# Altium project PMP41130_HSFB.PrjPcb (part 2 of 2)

## Sheet PMP41130_CTRL.SchDoc
size 431 x 279 mm; Date: Not shown in title block; ApprovedBy: Not shown in title block; CheckedBy: Not shown in title block; Author: Not shown in title block; CompanyName: Not shown in title block; Engineer: Not shown in title block; Organization: Not shown in title block; Address1: Not shown in title block; Address2: Not shown in title block; Address3: Not shown in title block; Address4: Not shown in title block; DocumentNumber: 2; Revision: Use project parameter SCH_Rev; SheetNumber: 3; SheetTotal: 5; PageSetup: Record=PageOptions¦CenterHorizontal=True¦CenterVertical=True¦PrintScale=1.00¦XCorrection=1.00¦YCorrection=1.00¦PrintKind=0¦BorderSize=5000000¦LeftOffset=0¦BottomOffset=0¦Orientation=2¦PaperLength=1000¦PaperWidth=1000¦Scale=100¦PaperSource=15¦PrintQuality=600¦MediaType=1¦DitherType=10¦PaperKind=Letter¦PrintScaleMode=1
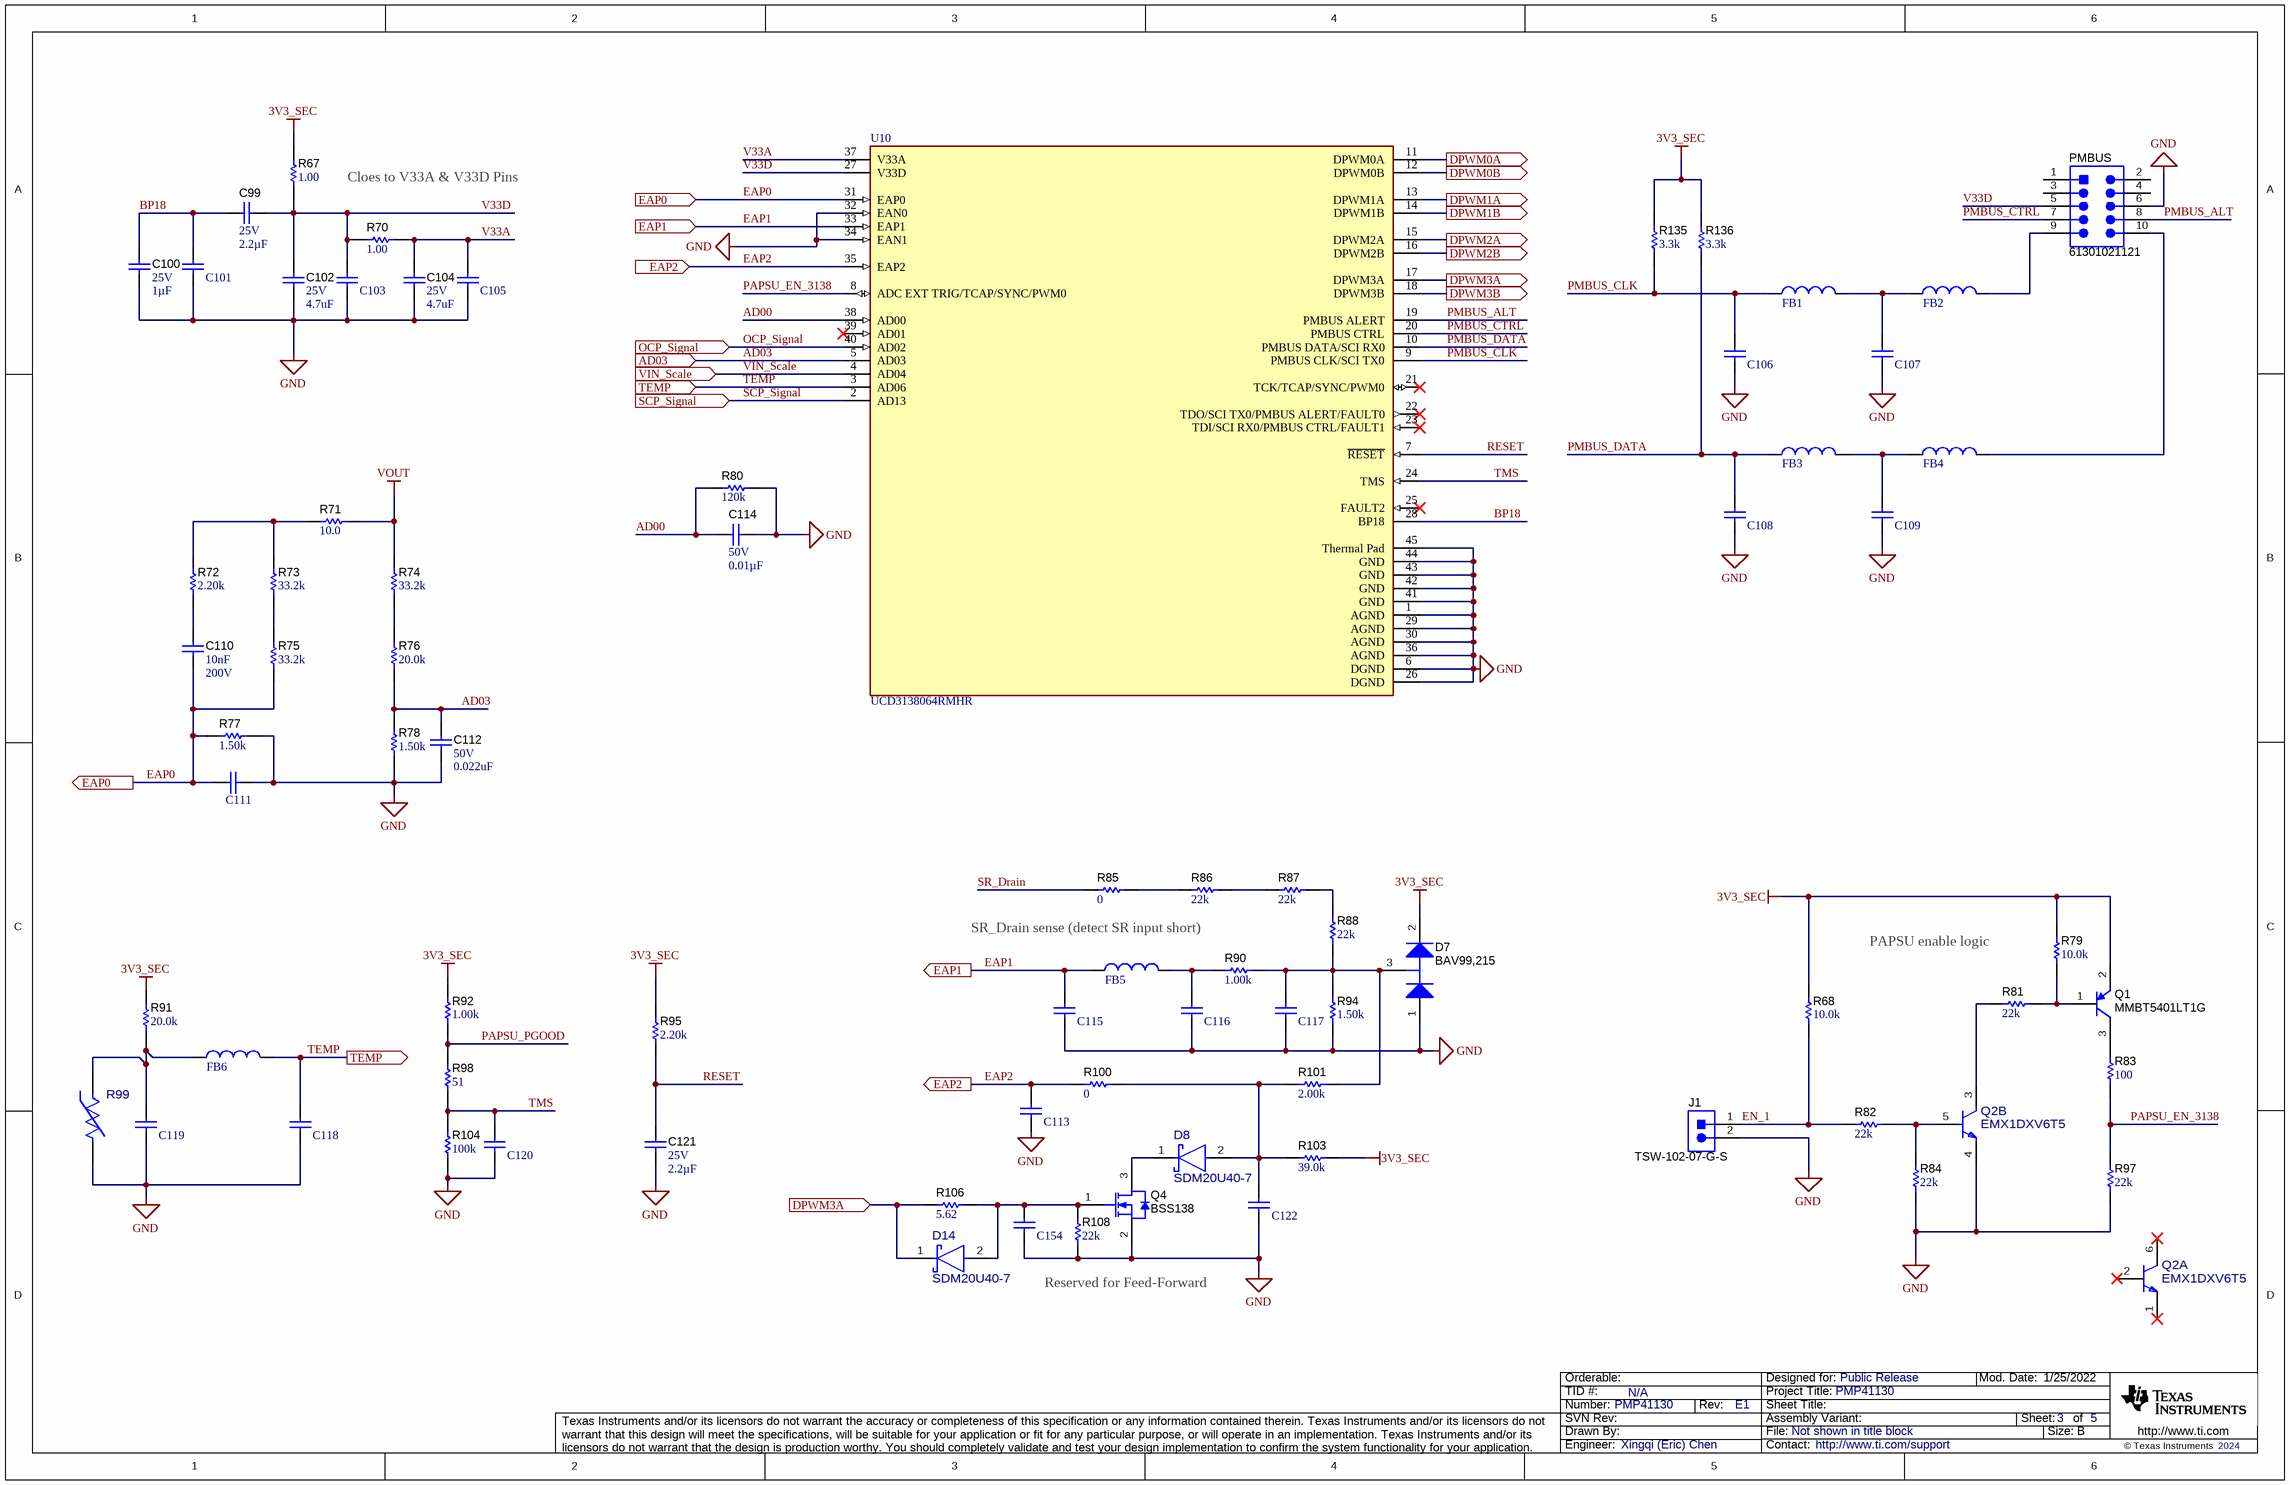
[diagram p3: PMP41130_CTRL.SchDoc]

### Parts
C99  VDC_V: 25V  ValueDisplayed: 2.2µF  [0402]  (hidden comment: GRM155R61E225ME15D)
C100  VDC_V: 25V  ValueDisplayed: 1µF  [0402]  (hidden comment: GRM155R61E105MA12D)
C101  885012205050  [WCAP-CSGP_0402_L1W0.5H0.5]  (value not drawn)
C102  VDC_V: 25V  ValueDisplayed: 4.7uF  [0402]  (hidden comment: GRM155R61E475ME15)
C103  885012205050  [WCAP-CSGP_0402_L1W0.5H0.5]  (value not drawn)
C104  VDC_V: 25V  ValueDisplayed: 4.7uF  [0402]  (hidden comment: GRM155R61E475ME15)
C105  885012205050  [WCAP-CSGP_0402_L1W0.5H0.5]  (value not drawn)
C106  885012005058  [WCAP-CSGP_0402_L1W0.5H0.5]  (value not drawn)
C107  885012005058  [WCAP-CSGP_0402_L1W0.5H0.5]  (value not drawn)
C108  885012005058  [WCAP-CSGP_0402_L1W0.5H0.5]  (value not drawn)
C109  885012005058  [WCAP-CSGP_0402_L1W0.5H0.5]  (value not drawn)
C110  Cap_F: 10nF  VDC_V: 200V  [0603]  (hidden comment: C0603C103K2RACTU)
C111  885012005067  [WCAP-CSGP_0402_L1W0.5H0.5]  (value not drawn)
C112  VDC_V: 50V  ValueDisplayed: 0.022uF  [0402]  (hidden comment: GRM155R71H223KA12D)
C113  885392005114  [WCAP-CSRF_0402_L1W0.5H0.5]  (value not drawn)
C114  VDC_V: 50V  ValueDisplayed: 0.01µF  [0402]  (hidden comment: CGA2B3X8R1H103K050BB)
C115  885012005055  [WCAP-CSGP_0402_L1W0.5H0.5]  (value not drawn)
C116  885012005055  [WCAP-CSGP_0402_L1W0.5H0.5]  (value not drawn)
C117  885012005055  [WCAP-CSGP_0402_L1W0.5H0.5]  (value not drawn)
C118  885012205092  [WCAP-CSGP_0402_L1W0.5H0.5]  (value not drawn)
C119  885012005067  [WCAP-CSGP_0402_L1W0.5H0.5]  (value not drawn)
C120  885012205044  [WCAP-CSGP_0402_L1W0.5H0.5]  (value not drawn)
C121  VDC_V: 25V  ValueDisplayed: 2.2µF  [0402]  (hidden comment: GRM155R61E225ME15D)
C122  885012205062  [WCAP-CSGP_0402_L1W0.5H0.5]  (value not drawn)
C154  885012205092  [WCAP-CSGP_0402_L1W0.5H0.5]  (value not drawn)
D7  BAV99,215  [SOT-23L]
D8  SDM20U40-7  [FP-SDM20U40-7_SOD523-MFG]
D14  SDM20U40-7  [FP-SDM20U40-7_SOD523-MFG]
FB1  7427927141  [WE-CBF_0402_L1W0.5H0.5_HS/WB]  (value not drawn)
FB2  7427927141  [WE-CBF_0402_L1W0.5H0.5_HS/WB]  (value not drawn)
FB3  7427927141  [WE-CBF_0402_L1W0.5H0.5_HS/WB]  (value not drawn)
FB4  7427927141  [WE-CBF_0402_L1W0.5H0.5_HS/WB]  (value not drawn)
FB5  7427927141  [WE-CBF_0402_L1W0.5H0.5_HS/WB]  (value not drawn)
FB6  7427927141  [WE-CBF_0402_L1W0.5H0.5_HS/WB]  (value not drawn)
J1  TSW-102-07-G-S  [TSW-102-07-G-S]
PMBUS  61301021121  [WURTH_61301021121]
Q1  MMBT5401LT1G  [SOT-23]
Q2  EMX1DXV6T5  [FP-EMX1DXV6T5_SOT563-MFG]  (parts A,B of 2)
Q4  BSS138  [SOT-23]
R67  ValueDisplayed: 1.00  [0402]  (hidden comment: CRCW04021R00FKED)
R68  ValueDisplayed: 10.0k  [0402]  (hidden comment: ERJ-2RKF1002X)
R70  ValueDisplayed: 1.00  [0402]  (hidden comment: CRCW04021R00FKED)
R71  ValueDisplayed: 10.0  [0402]  (hidden comment: RK73H1ETTP10R0F)
R72  ValueDisplayed: 2.20k  [0402]  (hidden comment: ERJ-2RKF2201X)
R73  ValueDisplayed: 33.2k  [0402]  (hidden comment: CRCW040233K2FKED)
R74  ValueDisplayed: 33.2k  [0402]  (hidden comment: CRCW040233K2FKED)
R75  ValueDisplayed: 33.2k  [0402]  (hidden comment: CRCW040233K2FKED)
R76  ValueDisplayed: 20.0k  [0402]  (hidden comment: RT0402BRD0720KL)
R77  ValueDisplayed: 1.50k  [0402]  (hidden comment: ERJ-2RKF1501X)
R78  ValueDisplayed: 1.50k  [0402]  (hidden comment: ERJ-2RKF1501X)
R79  ValueDisplayed: 10.0k  [0402]  (hidden comment: ERJ-2RKF1002X)
R80  ValueDisplayed: 120k  [0402]  (hidden comment: ERJ-2RKF1203X)
R81  ValueDisplayed: 22k  [0402]  (hidden comment: CRCW040222K0JNED)
R82  ValueDisplayed: 22k  [0402]  (hidden comment: CRCW040222K0JNED)
R83  ValueDisplayed: 100  [0402]  (hidden comment: RC0402FR-07100RL)
R84  ValueDisplayed: 22k  [0402]  (hidden comment: CRCW040222K0JNED)
R85  ValueDisplayed: 0  [0402]  (hidden comment: RC0402JR-070RL)
R86  ValueDisplayed: 22k  [0402]  (hidden comment: CRCW040222K0JNED)
R87  ValueDisplayed: 22k  [0402]  (hidden comment: CRCW040222K0JNED)
R88  ValueDisplayed: 22k  [0402]  (hidden comment: CRCW040222K0JNED)
R90  ValueDisplayed: 1.00k  [0402]  (hidden comment: ERJ-2RKF1001X)
R91  ValueDisplayed: 20.0k  [0402]  (hidden comment: RT0402BRD0720KL)
R92  ValueDisplayed: 1.00k  [0402]  (hidden comment: ERJ-2RKF1001X)
R94  ValueDisplayed: 1.50k  [0402]  (hidden comment: ERJ-2RKF1501X)
R95  ValueDisplayed: 2.20k  [0402]  (hidden comment: ERJ-2RKF2201X)
R97  ValueDisplayed: 22k  [0402]  (hidden comment: CRCW040222K0JNED)
R98  ValueDisplayed: 51  [0402]  (hidden comment: RC0402JR-0751RL)
R99  NCU15WF104E6SRC  [FP-NCU15WF104E6SRC_0402-MFG]  (value not drawn)
R100  ValueDisplayed: 0  [0402]  (hidden comment: RC0402JR-070RL)
R101  ValueDisplayed: 2.00k  [0402]  (hidden comment: RG1005P-202-B-T5)
R103  ValueDisplayed: 39.0k  [0402]  (hidden comment: ERJ2RKF3902X)
R104  ValueDisplayed: 100k  [0402]  (hidden comment: RC0402FR-07100KL)
R106  ValueDisplayed: 5.62  [0402]  (hidden comment: CRCW04025R62FKED)
R108  ValueDisplayed: 22k  [0402]  (hidden comment: CRCW040222K0JNED)
R135  ValueDisplayed: 3.3k  [0402]  (hidden comment: CRCW04023K30JNED)
R136  ValueDisplayed: 3.3k  [0402]  (hidden comment: CRCW04023K30JNED)
U10  UCD3138064RMHR  [FP-RMH0040A-MFG]

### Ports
AD03 (in), DPWM0A (out), DPWM0B (out), DPWM1A (out), DPWM1B (out), DPWM2A (out), DPWM2B (out), DPWM3A (in), DPWM3A (out), DPWM3B (out), EAP0 (in), EAP0 (out), EAP1 (in), EAP1 (out), EAP2 (in), EAP2 (out), OCP_Signal (in), SCP_Signal (in), TEMP (in), TEMP (out), VIN_Scale (in)

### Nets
3V3_SEC: D7.2(K) Q1.2(E) R67.2 R68.2 R79.2 R91.2 R92.2 R95.2 R103.2 R135.2 R136.2
GND: C100.2 C101.2 C102.2 C103.2 C104.2 C105.2 C106.2 C107.2 C108.2 C109.2 C111.2 C112.2 C113.2 C114.1 C115.2 C116.2 C117.2 C118.2 C119.2 C120.2 C121.2 C122.2 C154.2 D7.1(A) J1.2 PMBUS.6 Q2.4(EMITTER_2) Q4.2(S) R77.2 R78.1 R80.2 R84.1 R94.1 R97.1 R99.2 R104.1 R108.1 U10.1(AGND) U10.6(DGND) U10.26(DGND) U10.29(AGND) U10.30(AGND) U10.32(EAN0) U10.34(EAN1) U10.36(AGND) U10.41(GND) U10.42(GND) U10.43(GND) U10.44(GND) U10.45(Thermal_Pad)
VOUT: R71.2 R74.2
AD00: C114.2 R80.1 U10.38(AD00)
AD03: C112.1 R76.1 R78.2 U10.5(AD03) ; port AD03
BP18: C99.2 C100.1 C101.1 U10.28(BP18)
DPWM0A: U10.11(DPWM0A) ; port DPWM0A
DPWM0B: U10.12(DPWM0B) ; port DPWM0B
DPWM1A: U10.13(DPWM1A) ; port DPWM1A
DPWM1B: U10.14(DPWM1B) ; port DPWM1B
DPWM2A: U10.15(DPWM2A) ; port DPWM2A
DPWM2B: U10.16(DPWM2B) ; port DPWM2B
DPWM3A: D14.1(CATHODE) R106.1 U10.17(DPWM3A) ; port DPWM3A
DPWM3B: U10.18(DPWM3B) ; port DPWM3B
EAP0: C110.2 C111.1 R75.1 R77.1 U10.31(EAP0) ; port EAP0
EAP1: C115.1 FB5.1 U10.33(EAP1) ; port EAP1
EAP2: C113.1 R100.1 U10.35(EAP2) ; port EAP2
EN_1: J1.1 R68.1 R82.2
OCP_Signal: U10.40(AD02) ; port OCP_Signal
PAPSU_EN_3138: R83.1 R97.2 U10.8(ADC_EXT_TRIG/TCAP/SYNC/PWM0)
PAPSU_PGOOD: R92.1 R98.2
PMBUS_ALT: PMBUS.8 U10.19(PMBUS_ALERT)
PMBUS_CLK: C106.1 FB1.1 R135.1 U10.9(PMBUS_CLK/SCI_TX0)
PMBUS_CTRL: PMBUS.7 U10.20(PMBUS_CTRL)
PMBUS_DATA: C108.1 FB3.1 R136.1 U10.10(PMBUS_DATA/SCI_RX0)
RESET: C121.1 R95.1 U10.7(~{RESET})
SCP_Signal: U10.2(AD13) ; port SCP_Signal
SR_Drain: R85.1
TEMP: C118.1 FB6.2 U10.3(AD06) ; port TEMP
TMS: C120.1 R98.1 R104.2 U10.24(TMS)
V33A: C104.1 C105.1 R70.2 U10.37(V33A)
V33D: C99.1 C102.1 C103.1 PMBUS.5 R67.1 R70.1 U10.27(V33D)
VIN_Scale: U10.4(AD04) ; port VIN_Scale
NetC107_1: C107.1 FB1.2 FB2.1
NetC109_1: C109.1 FB3.2 FB4.1
NetC110_1: C110.1 R72.1
NetC116_1: C116.1 FB5.2 R90.1
NetC117_1: C117.1 D7.3(C) R88.1 R90.2 R94.2 R101.2
NetC119_1: C119.1 FB6.1 R91.1 R99.1
NetC122_1: C122.1 D8.2(ANODE) R100.2 R101.1 R103.1
NetC154_1: C154.1 D14.2(ANODE) Q4.1(G) R106.2 R108.2
NetD8_1: D8.1(CATHODE) Q4.3(D)
NetFB2_2: FB2.2 PMBUS.9
NetFB4_2: FB4.2 PMBUS.10
NetQ1_1: Q1.1(B) R79.1 R81.2
NetQ1_3: Q1.3(C) R83.2
NetQ2_3: Q2.3(COLLECTOR_2) R81.1
NetQ2_5: Q2.5(BASE_2) R82.1 R84.2
NetR71_1: R71.1 R72.2 R73.2
NetR73_1: R73.1 R75.2
NetR74_1: R74.1 R76.2
NetR85_2: R85.2 R86.1
NetR86_2: R86.2 R87.1
NetR87_2: R87.2 R88.2

Not connected (* = marked no-connect by the designer): PMBUS 1 2 3 4; Q2 1(EMITTER_1)* 2(BASE_1)* 6(COLLECTOR_1)*; U10 21(TCK/TCAP/SYNC/PWM0)* 22(TDO/SCI_TX0/PMBUS_ALERT/FAULT0)* 23(TDI/SCI_RX0/PMBUS_CTRL/FAULT1)* 25(FAULT2)* 39(AD01)*

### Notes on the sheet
- Cloes to V33A & V33D Pins
- SR_Drain sense (detect SR input short)
- PAPSU enable logic
- Reserved for Feed-Forward

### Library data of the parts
C99 C121 = CMP-0081010-1: CAP, CERM, 2.2 µF, 25 V,+/- 20%, X5R, 0402; Manufacturer: MuRata; SizeAreaWB_mm2: 3; SizeArea_mm2: 0.5; AEC Qualified: N; AEC Category: Q200; Value: 2.2uF; TaMax_C: 85°C; SizeZ_mm: 0.6; TaMin_C: -55°C; U/M: EA; SizeX_mm: 1
C100 = CMP-0078625-1: CAP, CERM, 1 µF, 25 V,+/- 20%, X5R, 0402; Manufacturer: MuRata; SizeAreaWB_mm2: 3; SizeArea_mm2: 0.5; AEC Qualified: N; AEC Category: Q200; Value: 1uF; TaMax_C: 85°C; SizeZ_mm: 0.6; TaMin_C: -55°C; U/M: EA; SizeX_mm: 1
C101 C103 C105 = CMP-0119280-1: WCAP-CSGP Multilayer Ceramic Chip Capacitor, General Purpose, size 0402, X7R, 10nF, 25VDC; Manufacturer: Wurth Elektronik; Capacitance Tolerance: +/-10%; Case/Size Code: 0402; Dissipation Factor: 3.5%; Insulation Resistance: 10GOhm; Rated Voltage (DC): 25V; Technical Reference: X7R0402103K025DFCT10000
C102 C104 = CMP-0006612-2: CAP, CERM, 4.7 uF, 25 V, +/- 20%, X5R, 0402; Manufacturer: MuRata; TaMin_C: -55°C; Polarized: N; SizeAreaWB_mm2: 3; Value1: Unknown; U/M: EA; Value: 4.7uF; TaMax_C: 85°C; SizeZ_mm: 0.6; SizeX_mm: 1; SizeY_mm: 0.5; Cap_F: 4.7µF; AEC Category: Q200
C106-C109 = CMP-0104156-1: WCAP-CSGP Multilayer Ceramic Chip Capacitor, General Purpose, size 0402, NP0, 33pF, 50VDC; Manufacturer: Wurth Elektronik; Capacitance Tolerance: +/-5%; Case/Size Code: 0402; Insulation Resistance: 10GOhm; Q Factor: 1000; Rated Voltage (DC): 50V; Technical Reference: NP00402330J050DFCT10000
C110 = CMP-0006852-4: CAP, CERM, 0.01 uF, 200 V, +/- 10%, X7R, 0603; Manufacturer: Kemet; TaMin_C: -55°C; Polarized: N; SizeAreaWB_mm2: 4.68; Value1: Unknown; U/M: EA; Value: 0.01uF; TaMax_C: 125°C; SizeZ_mm: 1; SizeX_mm: 1.6; SizeY_mm: 0.8; SizeArea_mm2: 1.28; AEC Category: Q200
C111 C119 = CMP-0107736-1: WCAP-CSGP Multilayer Ceramic Chip Capacitor, General Purpose, size 0402, NP0, 1nF, 50VDC; Manufacturer: Wurth Elektronik; Capacitance Tolerance: +/-5%; Case/Size Code: 0402; Insulation Resistance: 10GOhm; Q Factor: 1000; Rated Voltage (DC): 50V; Technical Reference: NP00402102J050DFCT10000
C112 = CMP-0006684-2: CAP, CERM, 0.022 uF, 50 V, +/- 10%, X7R, 0402; Manufacturer: MuRata; TaMin_C: -55°C; Polarized: N; SizeAreaWB_mm2: 3; Value1: Unknown; U/M: EA; TaMax_C: 125°C; SizeZ_mm: 0.6; SizeX_mm: 1; SizeY_mm: 0.5; Cap_F: 22nF; AEC Category: Q200
C113 = CMP-0116016-1: WCAP-CSRF Multilayer Ceramic Chip Capacitor, High Frequency, size 0402, NP0 Class I, 22pF, 50VDC; Manufacturer: Wurth Elektronik; Capacitance Tolerance: +/-5%; Case/Size Code: 0402; Insulation Resistance: 10GOhm; Q Factor: 840; Rated Voltage (DC): 50V; Technical Reference: NP00402220J050DFCT1R000
C114 = CMP-0078224-1: CAP, CERM, 0.01 µF, 50 V,+/- 10%, X8R, AEC-Q200 Grade 0, 0402; Manufacturer: TDK; TaMin_C: -55°C; Polarized: N; SizeAreaWB_mm2: 3; U/M: EA; Value: 0.01uF; TaMax_C: 150°C; SizeZ_mm: 0.6; SizeX_mm: 1; SizeY_mm: 0.5; AEC Qualified: Y; Cap_F: 10nF; AEC Grade: 0; AEC Category: Q200
C115-C117 = CMP-0111322-1: WCAP-CSGP Multilayer Ceramic Chip Capacitor, General Purpose, size 0402, NP0, 10pF, 50VDC; Manufacturer: Wurth Elektronik; Capacitance Tolerance: +/-5%; Case/Size Code: 0402; Insulation Resistance: 10GOhm; Q Factor: 600; Rated Voltage (DC): 50V; Technical Reference: NP00402100J050DFCT10000
C118 C154 = CMP-0111809-1: WCAP-CSGP Multilayer Ceramic Chip Capacitor, General Purpose, size 0402, X7R, 100nF, 50VDC; Manufacturer: Wurth Elektronik; Capacitance Tolerance: +/-5%; Case/Size Code: 0402; Dissipation Factor: 10%; Insulation Resistance: 0.5GOhm; Rated Voltage (DC): 50V; Technical Reference: X7R0402104J050DFCT10000
C120 = CMP-0119274-1: WCAP-CSGP Multilayer Ceramic Chip Capacitor, General Purpose, size 0402, X7R, 1nF, 25VDC; Manufacturer: Wurth Elektronik; Capacitance Tolerance: +/-10%; Case/Size Code: 0402; Dissipation Factor: 3.5%; Insulation Resistance: 10GOhm; Rated Voltage (DC): 25V; Technical Reference: X7R0402102K025DFCT10000
C122 = CMP-0053546-1: WCAP-CSGP Multilayer Ceramic Chip Capacitor, General Purpose, size 0402, X7R, 1.5nF, 50VDC; Manufacturer: Wurth Elektronik; Capacitance Tolerance: +/-10%; Case/Size Code: 0402; Dissipation Factor: 2.5%; Insulation Resistance: 10GOhm; Rated Voltage (DC): 50V; Technical Reference: X7R0402152K050DFCT10000
D7 = CMP-0076925-2: Diode, Switching, 100 V, 0.215 A, SOT-23; Manufacturer: Nexperia; SizeY_mm: 3.0; SizeZ_mm: 1.1; Green_REACh: Incomplete; Value: 100V; Io_A: 215mA; SizeArea_mm2: 7.5; AEC Category: Q101; Green_Lifecycle: Not Set; Vf_V: 1.25V; Value1: 0.215A; SizeX_mm: 2.5; TJmax_C: 150°C; SizeAreaWB_mm2: 14.0
D8 D14 = CMP-0122254-1: Diode Schottky 40V 0.25A 2-Pin SOD-523 T/R; Manufacturer: Diodes Inc.; AEC Qualified: Yes; SizeZ_mm: 0.65mm; TJmax_C: 125°C; AEC Grade: Grade 1; Cap_F: 50pF; Forward Current: 250mA; Max Surge Forward Current: 1A; Peak Reverse Current: 5uA
FB1-FB6 = CMP-0066373-1: WE-CBF SMT EMI Suppression Ferrite Bead, size 0402, 470Ohm, 0.62A; Manufacturer: Wurth Elektronik; Case/Size Code: 0402; DC Resistance Max: 0.45Ohm; Impedance Max: 1200Ohm; Impedance Max Test Condition: 300MHz; Type: High Speed
J1 = CMP-0075405-3: Header, 100mil, 2x1, Gold, TH; Manufacturer: Samtec; Current_A: 6.3A; Green_Lifecycle: Active; Pitch_mm: 2.54; Cert_CSA: Y; Cert_VDE: N; Green_REACh: Passed; Row_Count: 1; Gender: Male; Voltage_V: 550V
PMBUS = CMP-0054806-3: Header, 2.54 mm, 5x2, Gold, TH; Manufacturer: Wurth Elektronik; Green_Lifecycle: Active; Green_REACh: Passed; Cert_UL: Y; Current_A: 3A; Gender: Male; Pitch_mm: 2.54; Row_Count: 2; Shrouded: N; Voltage_V: 250V
Q1 = CMP-0000333-2: Transistor, PNP, 150 V, 0.5 A, SOT-23; Manufacturer: ON Semiconductor; TaMax_C: 150°C; Value2: 240; Value1: 0.5 A; Vcesat1_V: 5dV; SizeX_mm: 2.5; SizeY_mm: 3; TaMin_C: -55°C; IcRated_A: 5dA; CompType: BJT; SizeZ_mm: 1.1; Value: 150 V; SizeArea_mm2: 7.5; NPN: 0; Vceo_V: 150V; PNP: 1; AEC Category: Q101; SizeAreaWB_mm2: 14; U/M: EA
Q2 = CMP-0122249-1: TRANS ARR 2NPN 50V 100MA SOT563; Manufacturer: On Semiconductor; AEC Qualified: No; HfeMax: 560; NPN: 2; SizeZ_mm: 0.6mm; Vcesat1_V: 400mV; Ciiva Ids: 3224943; Collector Base Voltage: 60V; Emitter Base Voltage: 7V; Hfe Min: 120; Hfe Testic: 1mA; Hfe Testvce: 6V; Import Ts: 1521845472; Power_W: 500mW; Rthja Max: 250°C/W; TJmax_C: +150°C; Unity Gain Freq: 180MHz
Q4 = CMP-0000755-1: MOSFET, N-CH, 50 V, 0.22 A, SOT-23; Alternate Manufacturer: None; Manufacturer: Fairchild Semiconductor; SizeZ_mm: 1.1; ChType: N; Value2: 1.7 nC; VdsMax_V: 50V; SizeX_mm: 2.5; SizeY_mm: 3; Vgs_V: 20V; Value: 50V; Rdson45_ohm: 6; SizeArea_mm2: 7.5; AEC Category: Q101; IdsMax_A: 2.2dA; SizeAreaWB_mm2: 14; U/M: EA; QgTyp_nC: 1.7
R67 R70 = CMP-0026129-2: RES, 1.00, 1%, 0.063 W, AEC-Q200 Grade 0, 0402; Manufacturer: Vishay-Dale; Power_W: 63mW; TempCo: 100 ppm/C; Value_Code: 1R00; Value: 1.00; EIA_Code: E96; Res_ohm: 1; SizeY_mm: 0.5; SizeZ_mm: 0.6; Value2: 0.063W; AEC Qualified: Y; VDC_V: 50V; AEC Category: Q200; AEC Grade: 0
R68 R79 = CMP-0026658-1: RES, 10.0 k, 1%, 0.1 W, 0402; Manufacturer: Panasonic; Power_W: 100mW; TempCo: 100 ppm/C; Value_Code: 10k0; U/M: EA; Value: 10.0k; EIA_Code: E96; Res_ohm: 10k; SizeX_mm: 1; SizeY_mm: 0.5; SizeZ_mm: 0.6; Value2: 0.1W; VDC_V: 50V; AEC Category: Q200
R71 = CMP-0026749-1: RES, 10.0, 1%, 0.063 W, 0402; Manufacturer: KOA Speer; Power_W: 63mW; TempCo: 100 ppm/C; Value_Code: 10R0; U/M: EA; Value: 10.0; EIA_Code: E96; Res_ohm: 10; SizeX_mm: 1; SizeY_mm: 0.5; SizeZ_mm: 0.6; Value2: 0.063W; AEC Qualified: N; VDC_V: 50V; AEC Category: Q200
R72 R95 = CMP-0026681-1: RES, 2.20 k, 1%, 0.1 W, 0402; Manufacturer: Panasonic; Power_W: 100mW; TempCo: 100 ppm/C; Value_Code: 2k20; U/M: EA; Value: 2.20k; Res_ohm: 2.2k; SizeX_mm: 1; SizeY_mm: 0.5; SizeZ_mm: 0.6; Value2: 0.1W; VDC_V: 50V; AEC Category: Q200
R73-R75 = CMP-0026298-2: RES, 33.2 k, 1%, 0.063 W, AEC-Q200 Grade 0, 0402; Manufacturer: Vishay-Dale; Power_W: 63mW; TempCo: 100 ppm/C; Value_Code: 33k2; Value: 33.2k; EIA_Code: E96; SizeX_mm: 1; SizeY_mm: 0.5; SizeZ_mm: 0.6; Value2: 0.063W; AEC Qualified: Y; VDC_V: 50V; AEC Category: Q200; AEC Grade: 0
R76 R91 = CMP-0065358-1: RES, 20.0 k, .1%, .0625 W, 0402; Manufacturer: Yageo America; Power_W: 62.5mW; TempCo: 25 ppm/C; Value_Code: 20k0; U/M: EA; Value: 20.0k; EIA_Code: E192; Tolerance_%: 0.1%; Res_ohm: 20k; SizeX_mm: 1.0; SizeY_mm: 0.5; SizeZ_mm: 0.6; Value2: .0625W; VDC_V: 50V; AEC Category: Q200
R77 R78 R94 = CMP-0026668-1: RES, 1.50 k, 1%, 0.1 W, AEC-Q200 Grade 0, 0402; Manufacturer: Panasonic; Power_W: 100mW; TempCo: 100 ppm/C; Value_Code: 1k50; U/M: EA; Value: 1.50k; EIA_Code: E96; Res_ohm: 1.5k; SizeX_mm: 1; SizeY_mm: 0.5; SizeZ_mm: 0.6; Value2: 0.1W; AEC Qualified: Y; VDC_V: 50V; AEC Grade: 0; AEC Category: Q200
R80 = CMP-0026663-1: RES, 120 k, 1%, 0.1 W, AEC-Q200 Grade 0, 0402; Manufacturer: Panasonic; Power_W: 100mW; TempCo: 100 ppm/C; U/M: EA; Value: 120k; SizeX_mm: 1; SizeY_mm: 0.5; SizeZ_mm: 0.6; Value2: 0.1W; AEC Qualified: Y; VDC_V: 50V; AEC Grade: 0; AEC Category: Q200
R81 R82 R84 R86-R88 R97 R108 = CMP-0026879-3: RES, 22 k, 5%, 0.063 W, AEC-Q200 Grade 0, 0402; Manufacturer: Vishay-Dale; Power_W: 63mW; TempCo: 200 ppm/C; Value_Code: 22k0; Value: 22k; EIA_Code: E24; SizeX_mm: 1; SizeY_mm: 0.5; SizeZ_mm: 0.6; Value2: 0.063W; AEC Qualified: Y; VDC_V: 50V; AEC Category: Q200; AEC Grade: 0
R83 = CMP-0026722-1: RES, 100, 1%, 0.063 W, 0402; Manufacturer: Yageo America; Power_W: 63mW; TempCo: 100 ppm/C; Value_Code: 100R; U/M: EA; Value: 100; EIA_Code: E96; SizeX_mm: 1; SizeY_mm: 0.5; SizeZ_mm: 0.6; Value2: 0.063W; AEC Qualified: N; VDC_V: 50V; AEC Category: Q200
R85 R100 = CMP-0027004-2: RES, 0, 5%, 0.063 W, 0402; Manufacturer: Yageo America; Power_W: 63mW; TempCo: 200 ppm/C; Value_Code: 0000; U/M: EA; Value: 0; EIA_Code: E24; SizeX_mm: 1; SizeY_mm: 0.5; SizeZ_mm: 0.6; Value2: 0.063W; VDC_V: 50V; AEC Category: Q200
R90 R92 = CMP-0026657-1: RES, 1.00 k, 1%, 0.1 W, 0402; Manufacturer: Panasonic; Power_W: 100mW; TempCo: 100 ppm/C; Value_Code: 1k00; U/M: EA; Value: 1.00k; EIA_Code: E96; Res_ohm: 1k; SizeX_mm: 1; SizeY_mm: 0.5; SizeZ_mm: 0.6; Value2: 0.1W; VDC_V: 50V; AEC Category: Q200
R98 = CMP-0027006-2: RES, 51, 5%, 0.0625 W, 0402; Manufacturer: Yageo America; Power_W: 62.5mW; TempCo: 100 ppm/C; Value_Code: 51R0; U/M: EA; Value: 51; EIA_Code: E24; SizeX_mm: 1; SizeY_mm: 0.5; SizeZ_mm: 0.6; AEC Qualified: N; VDC_V: 50V; AEC Category: Q200
R99 = CMP-0122260-1: NTC Thermistor for Temperature Sensor, Automotive, 0402, 100kΩ, 3%, 0.032mA, 5V; Manufacturer: Murata; SizeZ_mm: 0.55mm; Value: 100k; AEC Grade: Grade 1; AEC Qualified: Yes; B 25 100: 4334K; B 25 50: 4250K; B 25 85: 4311K; B Tolerance: 1%
R101 = CMP-0026816-1: RES, 2.00 k, 0.1%, 0.063 W, 0402; Manufacturer: Susumu Co Ltd; Power_W: 63mW; TempCo: 25 ppm/C; Value_Code: 2k00; U/M: EA; Value: 2.00k; EIA_Code: E192; Res_ohm: 2k; SizeX_mm: 1; SizeY_mm: 0.5; SizeZ_mm: 0.6; Value2: 0.063W; AEC Category: Q200
R103 = CMP-0081725-1: RES, 39.0 k, 1%, 0.1 W, AEC-Q200 Grade 0, 0402; Manufacturer: Panasonic; Power_W: 100mW; TempCo: 100 ppm/C; SizeAreaWB_mm2: 3; Value_Code: 39k0; Value: 39.0k; Res_ohm: 39k; SizeX_mm: 1; SizeY_mm: 0.5; SizeZ_mm: 0.6; Value2: 0.1W; AEC Qualified: Y; AEC Grade: 0; AEC Category: Q200
R104 = CMP-0026721-1: RES, 100 k, 1%, 0.0625 W, 0402; Manufacturer: Yageo America; Power_W: 62.5mW; TempCo: 100 ppm/C; U/M: EA; Value: 100k; EIA_Code: E96; SizeX_mm: 1; SizeY_mm: 0.5; SizeZ_mm: 0.6; AEC Qualified: N; VDC_V: 50V; AEC Category: Q200
R106 = CMP-0026481-2: RES, 5.62, 1%, 0.063 W, AEC-Q200 Grade 0, 0402; Manufacturer: Vishay-Dale; Power_W: 63mW; TempCo: 100 ppm/C; Value_Code: 5R62; Value: 5.62; EIA_Code: E96; SizeX_mm: 1; SizeY_mm: 0.5; SizeZ_mm: 0.6; Value2: 0.063W; AEC Qualified: Y; VDC_V: 50V; AEC Category: Q200; AEC Grade: 0
R135 R136 = CMP-0026918-5: RES, 3.3 k, 5%, 0.063 W, AEC-Q200 Grade 0, 0402; Manufacturer: Vishay-Dale; Power_W: 63mW; TempCo: 200 ppm/C; Value_Code: 3k30; Value: 3.3k; EIA_Code: E24; SizeX_mm: 1; SizeY_mm: 0.5; SizeZ_mm: 0.6; Value2: 0.063W; AEC Qualified: Y; VDC_V: 50V; AEC Category: Q200; AEC Grade: 0
U10 = CMP-04910-000078-1: DIGITAL CONTROLLER; Number of Outputs: 8

## Sheet PMP41130_AUX.SchDoc
size 431 x 279 mm; Date: Not shown in title block; ApprovedBy: Not shown in title block; CheckedBy: Not shown in title block; Author: Not shown in title block; CompanyName: Not shown in title block; Engineer: Not shown in title block; Organization: Not shown in title block; Address1: Not shown in title block; Address2: Not shown in title block; Address3: Not shown in title block; Address4: Not shown in title block; DocumentNumber: 2; Revision: Use project parameter SCH_Rev; SheetNumber: 4; SheetTotal: 5; PageSetup: Record=PageOptions¦CenterHorizontal=True¦CenterVertical=True¦PrintScale=1.00¦XCorrection=1.00¦YCorrection=1.00¦PrintKind=0¦BorderSize=5000000¦LeftOffset=0¦BottomOffset=0¦Orientation=2¦PaperLength=1000¦PaperWidth=1000¦Scale=100¦PaperSource=15¦PrintQuality=600¦MediaType=1¦DitherType=10¦PaperKind=Letter¦PrintScaleMode=1
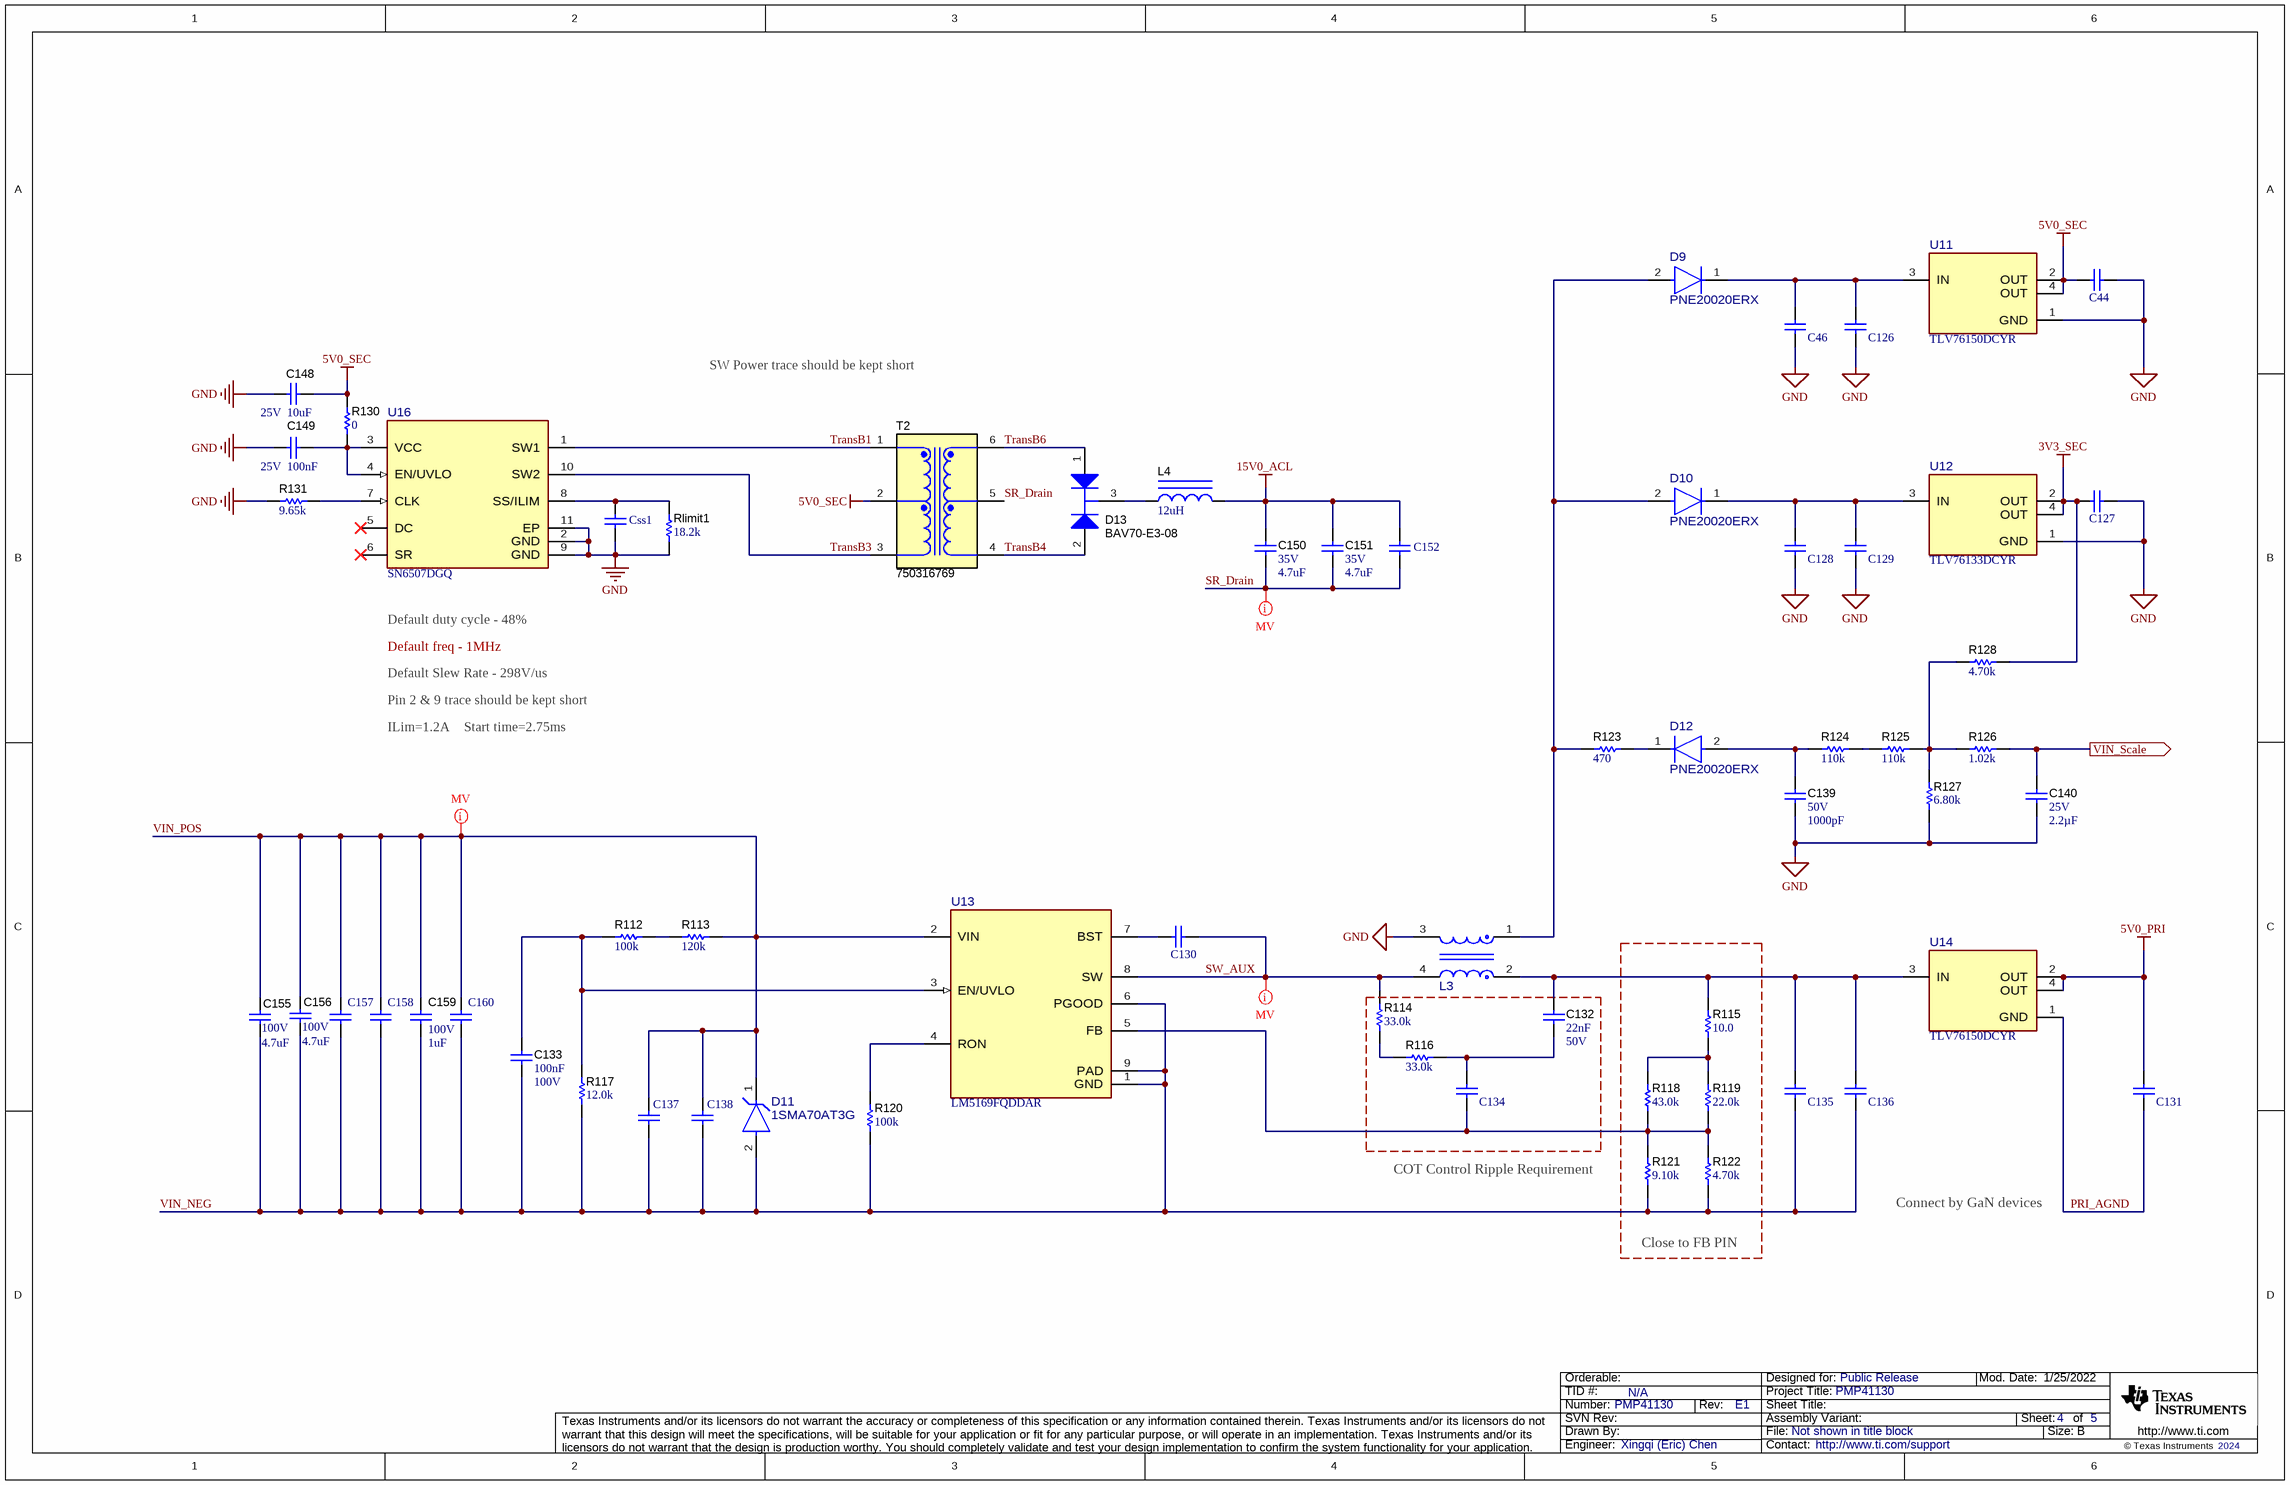
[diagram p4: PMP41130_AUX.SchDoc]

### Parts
C44  885012206027  [WCAP-CSGP_0603_L1.6W0.8H0.8_Reflow]  (value not drawn)
C46  885012208019  [WCAP-CSGP_1206_L3.2W1.6H1.6]  (value not drawn)
C126  885012206052  [WCAP-CSGP_0603_L1.6W0.8H0.8_Reflow]  (value not drawn)
C127  885012206027  [WCAP-CSGP_0603_L1.6W0.8H0.8_Reflow]  (value not drawn)
C128  885012208019  [WCAP-CSGP_1206_L3.2W1.6H1.6]  (value not drawn)
C129  885012206052  [WCAP-CSGP_0603_L1.6W0.8H0.8_Reflow]  (value not drawn)
C130  885012206085  [WCAP-CSGP_0603_L1.6W0.8H0.8_Reflow]  (value not drawn)
C131  885012206027  [WCAP-CSGP_0603_L1.6W0.8H0.8_Reflow]  (value not drawn)
C132  Cap_F: 22nF  VDC_V: 50V  [0603]  (hidden comment: C0603C223K5RACTU)
C133  Cap_F: 100nF  VDC_V: 100V  [0603]  (hidden comment: HMK107B7104KAHT)
C134  885012206085  [WCAP-CSGP_0603_L1.6W0.8H0.8_Reflow]  (value not drawn)
C135  885012208019  [WCAP-CSGP_1206_L3.2W1.6H1.6]  (value not drawn)
C136  885012206052  [WCAP-CSGP_0603_L1.6W0.8H0.8_Reflow]  (value not drawn)
C137  885012209071  [WCAP-CSGP_1210_L3.2W2.5H2.5]  (value not drawn)
C138  885012209071  [WCAP-CSGP_1210_L3.2W2.5H2.5]  (value not drawn)
C139  VDC_V: 50V  ValueDisplayed: 1000pF  [0603]  (hidden comment: C0603C102J5GAC)
C140  VDC_V: 25V  ValueDisplayed: 2.2µF  [0603]  (hidden comment: GRM188C71E225KE11D)
C148  VDC_V: 25V  ValueDisplayed: 10uF  [0805_HV]  (hidden comment: GRM21BR61E106MA73L)
C149  Cap_F: 100nF  VDC_V: 25V  [0805_HV]  (hidden comment: GRM21BR71E104KA01L)
C150  VDC_V: 35V  ValueDisplayed: 4.7uF  [0603]  (hidden comment: GRM188R6YA475KE15D)
C151  VDC_V: 35V  ValueDisplayed: 4.7uF  [0603]  (hidden comment: GRM188R6YA475KE15D)
C152  885012205092  [WCAP-CSGP_0402_L1W0.5H0.5]  (value not drawn)
C155  VDC_V: 100V  ValueDisplayed: 4.7uF  [1210]  (hidden comment: C3225X7S2A475K200AE)
C156  VDC_V: 100V  ValueDisplayed: 4.7uF  [1210]  (hidden comment: C3225X7S2A475K200AE)
C157  885012209071  [WCAP-CSGP_1210_L3.2W2.5H2.5]  (value not drawn)
C158  885012209071  [WCAP-CSGP_1210_L3.2W2.5H2.5]  (value not drawn)
C159  VDC_V: 100V  ValueDisplayed: 1uF  [1206]  (hidden comment: C3216X7R2A105M160AA)
C160  885012208118  [WCAP-CSGP_1206_L3.2W1.6H1.25]  (value not drawn)
Css1  885012207021  [WCAP-CSGP_0805_L2W1.25H1.25]  (value not drawn)
D9  PNE20020ERX  [FP-PNE20020ERX_SOD123W-MFG]
D10  PNE20020ERX  [FP-PNE20020ERX_SOD123W-MFG]
D11  1SMA70AT3G  [FP-1SMA70AT3G_SMA-MFG]
D12  PNE20020ERX  [FP-PNE20020ERX_SOD123W-MFG]
D13  BAV70-E3-08  [SOT-23L]
L3  MSD1260H-154KED  [FP-MSD1260H-154KED_SMT_CMC_12MM3_12MM3-MFG]  (value not drawn)
L4  ValueDisplayed: 12uH  [WE-TPC-LH]  (hidden comment: 744053120)
R112  ValueDisplayed: 100k  [0603]  (hidden comment: CRCW0603100KJNEAC)
R113  ValueDisplayed: 120k  [0603]  (hidden comment: RT0603BRD07120KL)
R114  ValueDisplayed: 33.0k  [0603]  (hidden comment: RC0603FR-0733KL)
R115  ValueDisplayed: 10.0  [0603]  (hidden comment: CRT0603-BY-10R0ELF)
R116  ValueDisplayed: 33.0k  [0603]  (hidden comment: RC0603FR-0733KL)
R117  ValueDisplayed: 12.0k  [0603]  (hidden comment: RT0603DRE0712KL)
R118  ValueDisplayed: 43.0k  [0603]  (hidden comment: RC0603FR-0743KL)
R119  ValueDisplayed: 22.0k  [0603]  (hidden comment: RC0603FR-0722KL)
R120  ValueDisplayed: 100k  [0603]  (hidden comment: CRCW0603100KJNEAC)
R121  ValueDisplayed: 9.10k  [0603]  (hidden comment: RC0603FR-079K1L)
R122  ValueDisplayed: 4.70k  [0603]  (hidden comment: RT0603BRD074K7L)
R123  ValueDisplayed: 470  [0603]  (hidden comment: RT0603BRD07470RL)
R124  ValueDisplayed: 110k  [0603]  (hidden comment: RC0603FR-07110KL)
R125  ValueDisplayed: 110k  [0603]  (hidden comment: RC0603FR-07110KL)
R126  ValueDisplayed: 1.02k  [0603]  (hidden comment: RT0603BRD071K02L)
R127  ValueDisplayed: 6.80k  [0603]  (hidden comment: RG1608P-682-B-T5)
R128  ValueDisplayed: 4.70k  [0603]  (hidden comment: RT0603BRD074K7L)
R130  ValueDisplayed: 0  [0805_HV]  (hidden comment: CRCW08050000Z0EAHP)
R131  ValueDisplayed: 9.65k  [0805_HV]  (hidden comment: RT0805BRD079K65L)
Rlimit1  ValueDisplayed: 18.2k  [0805_HV]  (hidden comment: RT0805BRD0718K2L)
T2  750316769  [Wurth_750316769]
U11  TLV76150DCYR  [DCY0004A-MFG]
U12  TLV76133DCYR  [DCY0004A-MFG]
U13  LM5169FQDDAR  [DDA0008E-MFG]
U14  TLV76150DCYR  [DCY0004A-MFG]
U16  SN6507DGQ  [DGQ0010D-MFG]

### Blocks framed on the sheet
Close to FB PIN: R115 R118 R119 R121 R122

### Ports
VIN_Scale (out)

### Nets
3V3_SEC: C127.1 R128.1 U12.2(OUT) U12.4(OUT)
5V0_PRI: C131.2 U14.2(OUT) U14.4(OUT)
5V0_SEC: C44.1 C148.1 R130.2 T2.2 U11.2(OUT) U11.4(OUT)
15V0_ACL: C150.1 C151.1 C152.1 L4.2
GND: C44.2 C46.2 C126.2 C127.2 C128.2 C129.2 C139.2 C140.2 C148.2 C149.1 Css1.2 L3.3 R127.1 R131.1 Rlimit1.1 U11.1(GND) U12.1(GND) U16.2(GND) U16.9(GND) U16.11(EP)
PRI_AGND: C131.1 U14.1(GND)
SR_Drain: C150.2 C151.2 C152.2 T2.5
SW_AUX: C130.2 L3.4 R114.2 U13.8(SW)
TransB1: T2.1 U16.1(SW1)
TransB3: T2.3 U16.10(SW2)
TransB4: D13.2(K) T2.4
TransB6: D13.1(A) T2.6
VIN_NEG: C133.2 C135.2 C136.2 C137.2 C138.2 C155.2 C156.2 C157.2 C158.2 C159.2 C160.1 D11.2(Anode) R117.1 R120.1 R121.1 R122.1 U13.1(GND) U13.6(PGOOD) U13.9(PAD)
VIN_POS: C137.1 C138.1 C155.1 C156.1 C157.1 C158.1 C159.1 C160.2 D11.1(Cathode) R113.2 U13.2(VIN)
VIN_Scale: C140.1 R126.2 ; port VIN_Scale
NetC46_1: C46.1 C126.1 D9.1(K) U11.3(IN)
NetC128_1: C128.1 C129.1 D10.1(K) U12.3(IN)
NetC130_1: C130.1 U13.7(BST)
NetC132_1: C132.1 C135.1 C136.1 L3.2 R115.2 U14.3(IN)
NetC132_2: C132.2 C134.1 R116.1
NetC133_1: C133.1 R112.1 R117.2 U13.3(EN/UVLO)
NetC134_2: C134.2 R118.1 R119.1 R121.2 R122.2 U13.5(FB)
NetC139_1: C139.1 D12.2(A) R124.1
NetC149_2: C149.2 R130.1 U16.3(VCC) U16.4(EN/UVLO)
NetCss1_1: Css1.1 Rlimit1.2 U16.8(SS/ILIM)
NetD9_2: D9.2(A) D10.2(A) L3.1 R123.1
NetD12_1: D12.1(K) R123.2
NetD13_3: D13.3(C) L4.1
NetR112_2: R112.2 R113.1
NetR114_1: R114.1 R116.2
NetR115_1: R115.1 R118.2 R119.2
NetR120_2: R120.2 U13.4(RON)
NetR124_2: R124.2 R125.1
NetR125_2: R125.2 R126.1 R127.2 R128.2
NetR131_2: R131.2 U16.7(CLK)

Not connected (* = marked no-connect by the designer): U16 5(DC)* 6(SR)*

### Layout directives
mark named MV: SR_Drain
net class MIDVOLTAGE: SW_AUX, VIN_POS

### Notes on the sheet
- SW Power trace should be kept short
- Default duty cycle - 48%
- Pin 2 & 9 trace should be kept short
- Default freq - 1MHz
- Default Slew Rate - 298V/us
- ILim=1.2A    Start time=2.75ms
- (near R121) COT Control Ripple Requirement
- Connect by GaN devices

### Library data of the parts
C44 C127 C131 = CMP-0115410-1: WCAP-CSGP Multilayer Ceramic Chip Capacitor, General Purpose, size 0603, X7R, 2.2µF, 10VDC; Manufacturer: Wurth Elektronik; Capacitance Tolerance: +/-10%; Case/Size Code: 0603; Dissipation Factor: 10%; Insulation Resistance: 0.02GOhm; Rated Voltage (DC): 10V; Technical Reference: X7R0603225K010DFCT10000
C46 C128 C135 = CMP-0108465-1: WCAP-CSGP Multilayer Ceramic Chip Capacitor, General Purpose, size 1206, X7R, 22µF, 10VDC; Manufacturer: Wurth Elektronik; Capacitance Tolerance: +/-10%; Case/Size Code: 1206; Dissipation Factor: 10%; Insulation Resistance: 0.005GOhm; Rated Voltage (DC): 10V; Technical Reference: X7R1206226K010DFCT10000
C126 C129 C136 = CMP-0115435-1: WCAP-CSGP Multilayer Ceramic Chip Capacitor, General Purpose, size 0603, X7R, 1µF, 16VDC; Manufacturer: Wurth Elektronik; Capacitance Tolerance: +/-10%; Case/Size Code: 0603; Dissipation Factor: 10%; Insulation Resistance: 0.1GOhm; Rated Voltage (DC): 16V; Technical Reference: X7R0603105K016DFCT10000
C130 C134 = CMP-0111894-1: WCAP-CSGP Multilayer Ceramic Chip Capacitor, General Purpose, size 0603, X7R, 2.2nF, 50VDC; Manufacturer: Wurth Elektronik; Capacitance Tolerance: +/-10%; Case/Size Code: 0603; Dissipation Factor: 2.5%; Insulation Resistance: 10GOhm; Rated Voltage (DC): 50V; Technical Reference: X7R0603222K050DFCT10000
C132 = CMP-0006901-4: CAP, CERM, 0.022 uF, 50 V, +/- 10%, X7R, 0603; Manufacturer: Kemet; TaMin_C: -55°C; Polarized: N; Value1: Unknown; U/M: EA; TaMax_C: 125°C; SizeAreaWB_mm2: 4.68; SizeZ_mm: 1; SizeX_mm: 1.6; SizeY_mm: 0.8; SizeArea_mm2: 1.28; AEC Category: Q200
C133 = CMP-0081011-1: CAP, CERM, 0.1 µF, 100 V,+/- 10%, X7R, AEC-Q200 Grade 1, 0603; Manufacturer: Taiyo Yuden; SizeAreaWB_mm2: 4.68; SizeArea_mm2: 1.28; AEC Qualified: Y; AEC Category: Q200; Value: 0.1uF; TaMax_C: 125°C; SizeZ_mm: 1; Polarized: N; TaMin_C: -55°C; SizeY_mm: 0.8; U/M: EA; SizeX_mm: 1.6; ValueDisplayed: 0.1µF
C137 C138 C157 C158 = CMP-0105033-1: WCAP-CSGP Multilayer Ceramic Chip Capacitor, General Purpose, size 1210, X7R, 2.2µF, 100VDC; Manufacturer: Wurth Elektronik; Capacitance Tolerance: +/-10%; Case/Size Code: 1210; Dissipation Factor: 5%; Insulation Resistance: 0.05GOhm; Rated Voltage (DC): 100V; Technical Reference: X7R1210225K100DFCT10000
C139 = CMP-0006842-4: CAP, CERM, 1000 pF, 50 V, +/- 5%, C0G/NP0, 0603; Manufacturer: Kemet; TaMin_C: -55°C; Polarized: N; SizeAreaWB_mm2: 4.68; Value1: Unknown; U/M: EA; Value: 1000pF; TaMax_C: 125°C; SizeZ_mm: 1; SizeX_mm: 1.6; SizeY_mm: 0.8; SizeArea_mm2: 1.28; Cap_F: 1nF; AEC Category: Q200
C140 = CMP-0075366-3: CAP, CERM, 2.2 µF, 25 V,+/- 10%, X7S, 0603; Manufacturer: MuRata; TaMin_C: -55°C; Polarized: N; SizeAreaWB_mm2: 4.68; U/M: EA; Value: 2.2uF; TaMax_C: 125°C; SizeZ_mm: 1.0; SizeX_mm: 1.6; SizeY_mm: 0.8; SizeArea_mm2: 1.28; AEC Category: Q200
C148 = CMP-0008303-3: CAP, CERM, 10 uF, 25 V, +/- 20%, X5R, 0805; Manufacturer: MuRata; SizeZ_mm: 1.45; U/M: EA; SizeAreaWB_mm2: 6.75; TaMin_C: -55°C; Value1: Unknown; Cap_F: 10µF; SizeX_mm: 2; Cap_Case: 0805; TaMax_C: 85°C; Polarized: N; SizeY_mm: 1.25; AEC Category: Q200; SizeArea_mm2: 2.5; Value: 10uF
C149 = CMP-0008335-2: CAP, CERM, 0.1 uF, 25 V, +/- 10%, X7R, 0805; Manufacturer: MuRata; TaMin_C: -55°C; Polarized: N; SizeAreaWB_mm2: 6.75; Value1: Unknown; U/M: EA; Value: 0.1uF; TaMax_C: 125°C; SizeZ_mm: 1.45; SizeX_mm: 2; SizeY_mm: 1.25; Cap_Case: 0805; SizeArea_mm2: 2.5; AEC Category: Q200
C150 C151 = CMP-0007357-5: CAP, CERM, 4.7 uF, 35 V, +/- 10%, X5R, 0603; Manufacturer: MuRata; TaMin_C: -55°C; Polarized: N; SizeAreaWB_mm2: 4.68; Value1: Unknown; U/M: EA; Value: 4.7uF; TaMax_C: 85°C; SizeZ_mm: 1; SizeX_mm: 1.6; SizeY_mm: 0.8; SizeArea_mm2: 1.28; Cap_F: 4.7µF; AEC Category: Q200
C152 = CMP-0111809-1: as C118 on sheet PMP41130_CTRL
C155 C156 = CMP-0009135-2: CAP, CERM, 4.7 uF, 100 V, +/- 10%, X7S, 1210; Manufacturer: TDK; TaMin_C: -55°C; Polarized: N; SizeAreaWB_mm2: 14.7; Value1: Unknown; U/M: EA; Value: 4.7uF; TaMax_C: 125°C; SizeZ_mm: 1.35; SizeX_mm: 3.2; SizeY_mm: 2.5; SizeArea_mm2: 8; Cap_F: 4.7µF; AEC Category: Q200
C159 = CMP-0008711-2: CAP, CERM, 1 uF, 100 V, +/- 20%, X7R, 1206; Manufacturer: TDK; TaMin_C: -55°C; Polarized: N; SizeAreaWB_mm2: 10.92; Value1: Unknown; U/M: EA; Value: 1uF; TaMax_C: 125°C; SizeZ_mm: 1.35; SizeX_mm: 3.2; SizeY_mm: 1.6; SizeArea_mm2: 5.12; Cap_F: 1µF; AEC Category: Q200
C160 = CMP-0119652-1: WCAP-CSGP Multilayer Ceramic Chip Capacitor, General Purpose, size 1206, X7R, 100nF, 100VDC; Manufacturer: Wurth Elektronik; Capacitance Tolerance: +/-10%; Case/Size Code: 1206; Dissipation Factor: 2.5%; Insulation Resistance: 1GOhm; Rated Voltage (DC): 100V; Technical Reference: X7R1206104K100DFCT10000
Css1 = CMP-0111941-1: WCAP-CSGP Multilayer Ceramic Chip Capacitor, General Purpose, size 0805, X7R, 680nF, 10VDC; Manufacturer: Wurth Elektronik; Capacitance Tolerance: +/-10%; Case/Size Code: 0805; Dissipation Factor: 5%; Insulation Resistance: 0.7GOhm; Rated Voltage (DC): 10V; Technical Reference: X7R0805684K010DFCT10000
D9 D10 D12 = CMP-0122261-1: Diode 200 V 2A Surface Mount SOD-123W; Manufacturer: Nexperia; AEC Qualified: No; SizeZ_mm: 1.1mm; TJmax_C: 175°C; Vf_V: 200V; Cap_F: 17pF; Max Surge Forward Current: 50A; Peak Reverse Current: 0.01uA; TaMax_C: +175°C; TaMin_C: -55°C
D11 = CMP-0122570-1: Diode TVS Single Uni-Dir 70V 400W Automotive 2-Pin SMA T/R; Manufacturer: Littelfuse; Obsolete Part: true; AEC Qualified: No; SizeZ_mm: 2.2mm; Ipp: 3.5A; Breakdown Voltage: 77.8V; Cap_F: 190pF; Clamping Voltage: 113V; Direction: Unidirectional; Number Of Channels: 1; Standoff Height: 0.05mm; TJmax_C: +150°C
D13 = CMP-0077061-2: Diode, Switching, 70 V, 0.25 A, AEC-Q101, SOT-23; Manufacturer: Vishay-Semiconductor; SizeZ_mm: 1.1; AEC Qualified: Y; Value: 70V; SizeY_mm: 3.0; Value2: 1.25V; SizeArea_mm2: 7.5; AEC Category: Q101; SizeAreaWB_mm2: 14.0; Value1: 0.25A; Io_A: 250mA; SizeX_mm: 2.5; Green_REACh: Incomplete; TJmax_C: 150°C; Green_Lifecycle: Not Set
L3 = CMP-0122580-1: Shielded Coupled Inductor 150uH 10% 100kHz 0.465Ohm 1.1A 12.3x12.3x6.2mm SMT AECQ200; Manufacturer: Coilcraft; DCR_ohm: 0.465; Ind_H: 150µH; SizeZ_mm: 6.2mm; AEC Qualified: Yes; AEC Grade: Grade 1; Isat: 1.2A; Material: Ferrite; Self Resonant Frequency: 5.4MHz; Shrouded: true; TaMax_C: +125°C; TaMin_C: -40°C
L4 = CMP-0064419-2: Inductor, Shielded Drum Core, Ferrite, 12 uH, 1.25 A, 0.06 ohm, SMD; Manufacturer: Wurth Elektronik; Isat: 1.25A @ 35% inductance drop; Irms: 1.46A @ 30C rise; Green_Lifecycle: Active; SizeAreaWB_mm2: 60.84; DCR_ohm: 0.06; Green_REACh: Passed; Value: 12uH; Imax_A: 1.25A; SizeZ_mm: 2.8; SizeX_mm: 5.8; SizeArea_mm2: 33.64; Ind_H: 12µH; AEC Category: Q200
R112 R120 = CMP-0082530-1: RES, 100 k, 5%, 0.1 W, 0603; Manufacturer: Vishay-Dale; Power_W: 100mW; TempCo: 200 ppm/C; SizeAreaWB_mm2: 4.68; Value: 100k; EIA_Code: E24; SizeX_mm: 1.6; SizeY_mm: 0.8; SizeZ_mm: 1; Value2: 0.1W; SizeArea_mm2: 1.28; AEC Qualified: N; VDC_V: 75V; AEC Category: Q200
R113 = CMP-0023690-3: RES, 120 k, 0.1%, 0.1 W, 0603; Manufacturer: Yageo America; Power_W: 100mW; TempCo: 25 ppm/C; U/M: EA; Value: 120k; EIA_Code: E192; SizeX_mm: 1.6; SizeY_mm: 0.8; SizeZ_mm: 1; Value2: 0.1W; SizeArea_mm2: 1.28; VDC_V: 75V; AEC Category: Q200
R114 R116 = CMP-0023037-5: RES, 33.0 k, 1%, 0.1 W, 0603; Manufacturer: Yageo; Power_W: 100mW; TempCo: 100 ppm/C; Value_Code: 33k0; Value: 33.0k; Res_ohm: 33k; SizeX_mm: 1.6; SizeY_mm: 0.8; SizeZ_mm: 1; Value2: 0.1W; SizeArea_mm2: 1.28; AEC Qualified: N; VDC_V: 75V; AEC Category: Q200; SizeAreaWB_mm2: 4.68
R115 = CMP-0023359-3: RES, 10.0, 0.1%, 0.1 W, 0603; Manufacturer: Bourns; Power_W: 100mW; TempCo: 25 ppm/C; Value_Code: 10R0; U/M: EA; Value: 10.0; EIA_Code: E192; Res_ohm: 10; SizeX_mm: 1.6; SizeY_mm: 0.8; SizeZ_mm: 1; Value2: 0.1W; SizeArea_mm2: 1.28; AEC Qualified: N; AEC Category: Q200
R117 = CMP-0024643-3: RES, 12.0 k, 0.5%, 0.1 W, 0603; Manufacturer: Yageo America; Power_W: 100mW; TempCo: 50 ppm/C; Value_Code: 12k0; U/M: EA; Value: 12.0k; EIA_Code: E192; Res_ohm: 12k; SizeX_mm: 1.6; SizeY_mm: 0.8; SizeZ_mm: 1; Value2: 0.1W; SizeArea_mm2: 1.28; VDC_V: 75V; AEC Category: Q200
R118 = CMP-0023113-5: RES, 43.0 k, 1%, 0.1 W, 0603; Manufacturer: Yageo; Power_W: 100mW; TempCo: 100 ppm/C; Value_Code: 43k0; Value: 43.0k; Res_ohm: 43k; SizeX_mm: 1.6; SizeY_mm: 0.8; SizeZ_mm: 1; Value2: 0.1W; SizeArea_mm2: 1.28; AEC Qualified: N; VDC_V: 75V; AEC Category: Q200; SizeAreaWB_mm2: 4.68
R119 = CMP-0022925-5: RES, 22.0 k, 1%, 0.1 W, 0603; Manufacturer: Yageo; Power_W: 100mW; TempCo: 100 ppm/C; Value_Code: 22k0; Value: 22.0k; Res_ohm: 22k; SizeX_mm: 1.6; SizeY_mm: 0.8; SizeZ_mm: 1; Value2: 0.1W; SizeArea_mm2: 1.28; AEC Qualified: N; VDC_V: 75V; AEC Category: Q200; SizeAreaWB_mm2: 4.68
R121 = CMP-0023333-5: RES, 9.10 k, 1%, 0.1 W, 0603; Manufacturer: Yageo; Power_W: 100mW; TempCo: 100 ppm/C; Value_Code: 9k10; Value: 9.10k; Res_ohm: 9.1k; SizeX_mm: 1.6; SizeY_mm: 0.8; SizeZ_mm: 1; Value2: 0.1W; SizeArea_mm2: 1.28; AEC Qualified: N; VDC_V: 75V; AEC Category: Q200; SizeAreaWB_mm2: 4.68
R122 R128 = CMP-0024300-2: RES, 4.70 k, 0.1%, 0.1 W, 0603; Manufacturer: Yageo America; Power_W: 100mW; TempCo: 25 ppm/C; Value_Code: 4k70; U/M: EA; Value: 4.70k; EIA_Code: E192; Res_ohm: 4.7k; SizeX_mm: 1.6; SizeY_mm: 0.8; SizeZ_mm: 1; Value2: 0.1W; SizeArea_mm2: 1.28; VDC_V: 75V; AEC Category: Q200
R123 = CMP-0024263-2: RES, 470, 0.1%, 0.1 W, 0603; Manufacturer: Yageo America; Power_W: 100mW; TempCo: 25 ppm/C; Value_Code: 470R; U/M: EA; Value: 470; EIA_Code: E192; SizeX_mm: 1.6; SizeY_mm: 0.8; SizeZ_mm: 1; Value2: 0.1W; SizeArea_mm2: 1.28; VDC_V: 75V; AEC Category: Q200
R124 R125 = CMP-0022752-4: RES, 110 k, 1%, 0.1 W, 0603; Manufacturer: Yageo; Power_W: 100mW; TempCo: 100 ppm/C; Value: 110k; EIA_Code: E96; SizeX_mm: 1.6; SizeY_mm: 0.8; SizeZ_mm: 1; Value2: 0.1W; SizeArea_mm2: 1.28; AEC Qualified: N; VDC_V: 75V; AEC Category: Q200; SizeAreaWB_mm2: 4.68
R126 = CMP-0023863-3: RES, 1.02 k, 0.1%, 0.1 W, 0603; Manufacturer: Yageo America; Power_W: 100mW; TempCo: 25 ppm/C; Value_Code: 1k02; U/M: EA; Value: 1.02k; EIA_Code: E192; SizeX_mm: 1.6; SizeY_mm: 0.8; SizeZ_mm: 1; Value2: 0.1W; SizeArea_mm2: 1.28; VDC_V: 75V; AEC Category: Q200
R127 = CMP-0023592-3: RES, 6.80 k, 0.1%, 0.1 W, 0603; Manufacturer: Susumu Co Ltd; Power_W: 100mW; TempCo: 25 ppm/C; Value_Code: 6k80; U/M: EA; Value: 6.80k; Res_ohm: 6.8k; SizeX_mm: 1.6; SizeY_mm: 0.8; SizeZ_mm: 1; Value2: 0.1W; SizeArea_mm2: 1.28; VDC_V: 75V; AEC Category: Q200
R130 = CMP-0020443-3: RES, 0, 5%, 0.333 W, AEC-Q200 Grade 0, 0805; Manufacturer: Vishay-Dale; Power_W: 333mW; TempCo: 200 ppm/C; Value_Code: 0000; Value: 0; EIA_Code: E24; SizeX_mm: 2; SizeY_mm: 1.25; SizeZ_mm: 1.45; Value2: 0.333W; SizeArea_mm2: 2.5; AEC Qualified: Y; AEC Category: Q200; VDC_V: 150V
R131 = CMP-0020429-1: RES, 9.65 k, 0.1%, 0.125 W, 0805; Manufacturer: Yageo America; Power_W: 125mW; TempCo: 25 ppm/C; Value_Code: 9k65; U/M: EA; Value: 9.65k; EIA_Code: E192; SizeX_mm: 2; SizeY_mm: 1.25; SizeZ_mm: 1.45; Value2: 0.125W; SizeArea_mm2: 2.5; VDC_V: 150V; AEC Category: Q200
Rlimit1 = CMP-0019644-2: RES, 18.2 k, 0.1%, 0.125 W, 0805; Manufacturer: Yageo America; Power_W: 125mW; TempCo: 25 ppm/C; Value_Code: 18k2; U/M: EA; Value: 18.2k; EIA_Code: E192; SizeX_mm: 2; SizeY_mm: 1.25; SizeZ_mm: 1.45; SizeArea_mm2: 2.5; VDC_V: 150V; AEC Category: Q200; Value2: 0.125W
T2 = CMP-0067603-1: Transformer, 350 uH, SMT; Manufacturer: Wurth Elektronik; SizeAreaWB_mm2: 105.1965; DCR_ohm: 6d; Value: 350uH; Lp: 350.0; SizeZ_mm: 4.19; SizeX_mm: 10.05; SizeY_mm: 6.73; Ns1toNp: 3.45; SizeArea_mm2: 67.6365; Ind_H: 350µH; Rsec1_ohm: 1.5
U11 U14 = CMP-0121358-1: 1-A 16-V high-PSRR linear voltage regulator; Manufacturer: Texas Instruments; SizeZ_mm: 1.8mm; AEC Qualified: No; Accuracy Percentage: 1%; Dropout Voltage: 0.9V; Max Supply Voltage: 16V; Min Supply Voltage: 6.5V; Nominal Supply Current: 65uA; Number Of Outputs: 1; Output Type: Fixed; Output Voltage: 5V; Standoff Height: 0.02mm; TJmax_C: +125°C
U12 = CMP-0122558-1: 1-A 16-V high-PSRR linear voltage regulator 4-SOT-223 -40 to 125; Manufacturer: Texas Instruments; SizeZ_mm: 1.8mm; AEC Qualified: No; Accuracy Percentage: 1%; Dropout Voltage: 0.9V; Max Supply Voltage: 16V; Min Supply Voltage: 4.8V; Nominal Supply Current: 65uA; Number Of Outputs: 1; Output Type: Fixed; Output Voltage: 3.3V; Standoff Height: 0.02mm; TJmax_C: +125°C
U13 = CMP-0090988-1: IC; Manufacturer: Texas Instruments; SizeZ_mm: 1.7mm; Standoff Height: 0mm; AEC Qualified: No
U16 = CMP-0092987-2: Low-Noise 36V Push-Pull Transformer Driver with Duty Cycle Control for Isolated Power Supplies; Manufacturer: Texas Instruments; TaMin_C: -55°C; AEC Qualified: No; TJmax_C: +150°C; TaMax_C: +125°C; CompType: IC; SizeZ_mm: 1.1mm; AEC Category: Q200; Standoff Height: 0.05mm

## Sheet PMP41130_Hardware.SchDoc
size 431 x 279 mm; Date: Not shown in title block; ApprovedBy: Not shown in title block; CheckedBy: Not shown in title block; Author: Not shown in title block; CompanyName: Not shown in title block; Engineer: Not shown in title block; Organization: Not shown in title block; Address1: Not shown in title block; Address2: Not shown in title block; Address3: Not shown in title block; Address4: Not shown in title block; DocumentNumber: 3; Revision: Use project parameter SCH_Rev; SheetNumber: 5; SheetTotal: 5; PageSetup: Record=PageOptions¦CenterHorizontal=True¦CenterVertical=True¦PrintScale=1.00¦XCorrection=1.00¦YCorrection=1.00¦PrintKind=0¦BorderSize=5000000¦LeftOffset=0¦BottomOffset=0¦Orientation=2¦PaperLength=1000¦PaperWidth=1000¦Scale=100¦PaperSource=15¦PrintQuality=600¦MediaType=1¦DitherType=10¦PaperKind=Letter¦PrintScaleMode=1
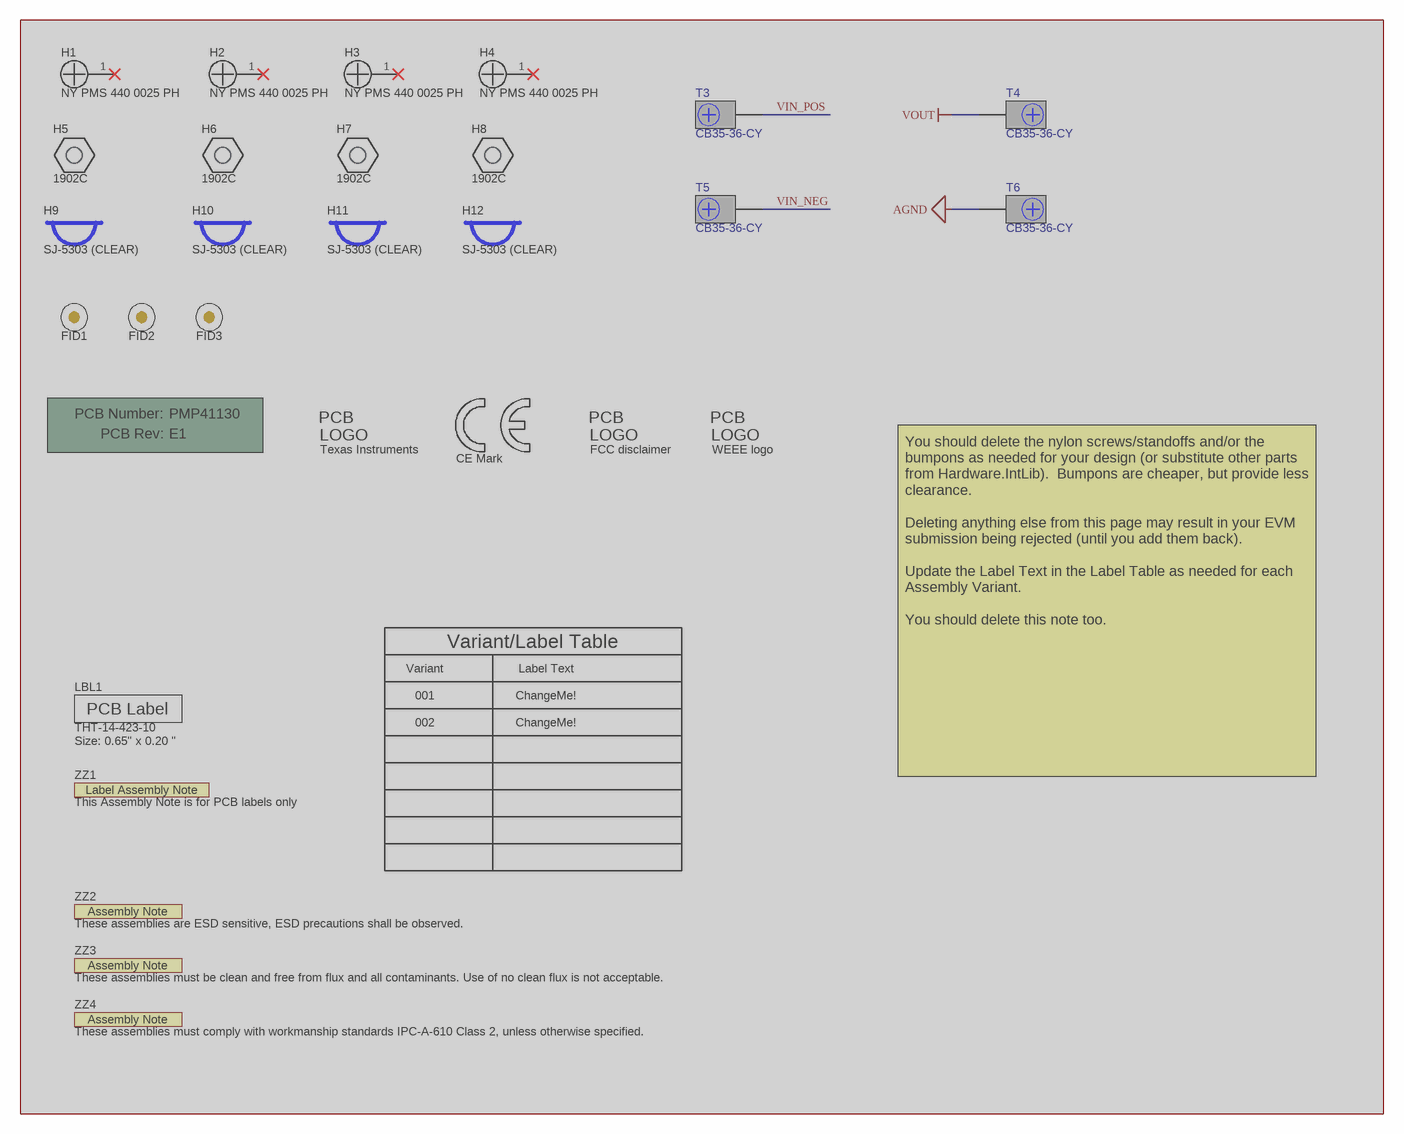
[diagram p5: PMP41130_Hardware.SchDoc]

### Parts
!PCB1  Printed Circuit Board  (value not drawn)  (mechanical)  (masked out: inside a compile mask, not in the netlist)
FID1  Fiducial  [Fiducial10-20]  (value not drawn)  (masked out: inside a compile mask, not in the netlist)
FID2  Fiducial  [Fiducial10-20]  (value not drawn)  (masked out: inside a compile mask, not in the netlist)
FID3  Fiducial  [Fiducial10-20]  (value not drawn)  (masked out: inside a compile mask, not in the netlist)
H1  NY PMS 440 0025 PH  [NY PMS 440 0025 PH]  (masked out: inside a compile mask, not in the netlist)
H2  NY PMS 440 0025 PH  [NY PMS 440 0025 PH]  (masked out: inside a compile mask, not in the netlist)
H3  NY PMS 440 0025 PH  [NY PMS 440 0025 PH]  (masked out: inside a compile mask, not in the netlist)
H4  NY PMS 440 0025 PH  [NY PMS 440 0025 PH]  (masked out: inside a compile mask, not in the netlist)
H5  1902C  [Keystone_1902C]  (masked out: inside a compile mask, not in the netlist)
H6  1902C  [Keystone_1902C]  (masked out: inside a compile mask, not in the netlist)
H7  1902C  [Keystone_1902C]  (masked out: inside a compile mask, not in the netlist)
H8  1902C  [Keystone_1902C]  (masked out: inside a compile mask, not in the netlist)
H9  SJ-5303 (CLEAR)  [Bumpon_SJ5003Transparent]  (masked out: inside a compile mask, not in the netlist)
H10  SJ-5303 (CLEAR)  [Bumpon_SJ5003Transparent]  (masked out: inside a compile mask, not in the netlist)
H11  SJ-5303 (CLEAR)  [Bumpon_SJ5003Transparent]  (masked out: inside a compile mask, not in the netlist)
H12  SJ-5303 (CLEAR)  [Bumpon_SJ5003Transparent]  (masked out: inside a compile mask, not in the netlist)
LBL1  THT-14-423-10  Note: Size: 0.65" x 0.20 "  [Label_650x200]  (masked out: inside a compile mask, not in the netlist)
Logo1  CE Mark  [CE_Mark_5mm]  (no BOM)  (masked out: inside a compile mask, not in the netlist)
Logo2  Texas Instruments  [TI_Stacked_Overlay_Small]  (no BOM)  (masked out: inside a compile mask, not in the netlist)
Logo3  FCC disclaimer  [FCC_disclaimer]  (no BOM)  (masked out: inside a compile mask, not in the netlist)
Logo4  WEEE logo  [WEEE_Minimum]  (no BOM)  (masked out: inside a compile mask, not in the netlist)
T3  CB35-36-CY  [CB35-36-CY]  (masked out: inside a compile mask, not in the netlist)
T4  CB35-36-CY  [CB35-36-CY]  (masked out: inside a compile mask, not in the netlist)
T5  CB35-36-CY  [CB35-36-CY]  (masked out: inside a compile mask, not in the netlist)
T6  CB35-36-CY  [CB35-36-CY]  (masked out: inside a compile mask, not in the netlist)
ZZ1  This Assembly Note is for PCB labels only  [AssemblyNoteLabel]  (no BOM)  (masked out: inside a compile mask, not in the netlist)
ZZ2  These assemblies are ESD sensitive, ESD precautions shall be observed.  [AssemblyNote]  (no BOM)  (masked out: inside a compile mask, not in the netlist)
ZZ3  These assemblies must be clean and free from flux and all contaminants. Use of no clean flux is not acceptable.  [AssemblyNote]  (no BOM)  (masked out: inside a compile mask, not in the netlist)
ZZ4  These assemblies must comply with workmanship standards IPC-A-610 Class 2, unless otherwise specified.  [AssemblyNote]  (no BOM)  (masked out: inside a compile mask, not in the netlist)

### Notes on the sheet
- Variant
- Variant/Label Table
- Label Text
- 001
- 002
- ChangeMe!
- You should delete the nylon screws/standoffs and/or the bumpons as needed for your design (or substitute other parts from Hardware.IntLib).  Bumpons are cheaper, but provide less clearance.
  Deleting anything else from this page may result in your EVM submission being rejected (until you add them back).
  Update the Label Text in the Label Table as needed for each Assembly Variant.
  You should delete this note too.

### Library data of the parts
!PCB1 = CMP-0003618-2: Manufacturer: Any; PartNumber: PMP41130
FID1-FID3 = CMP-0077181-1: Fiducial mark.  There is nothing to buy or mount.
H1-H4 = CMP-0003617-1: Machine Screw, Round, #4-40 x 1/4, Nylon, Philips panhead; Manufacturer: B&F Fastener Supply; CompType: Hardware
H5-H8 = CMP-0003610-1: Standoff, Hex, 0.5"L #4-40 Nylon; Manufacturer: Keystone; CompType: Hardware
H9-H12 = CMP-0003620-1: Bumpon, Hemisphere, 0.44 X 0.20, Clear; Manufacturer: 3M
LBL1 = CMP-0003625-1: Thermal Transfer Printable Labels, 0.650" W x 0.200" H - 10,000 per roll; Manufacturer: Brady; CompType: Label
Logo1 = CMP-0074844-1: SymbolCreator: a0412235
Logo2 = CMP-0074838-1: Texas Instrument Corporate Signature; SymbolCreator: a0412235; Lib Reference: TI_Logo; Library Reference: Logo
Logo3 = CMP-0074847-1: FCC_disclaimer; Library Reference: Logo
Logo4 = CMP-0074769-1
T3-T6 = CMP-0055442-1: Terminal 50A Lug; Manufacturer: Panduit; CNHeader: FALSE; Green_Lifecycle: Not Set; Cert_CULUS: Y; Green_REACh: Incomplete; Voltage_V: 600V; CompType: Screw Terminal; ContactFinish: Copper
ZZ1 = CMP-0003616-3
ZZ2 = CMP-0077236-1
ZZ3 = CMP-0077237-1
ZZ4 = CMP-0077238-1

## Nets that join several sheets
3V3_SEC: PMP41130_PWR (R40.2 R49.2 R62.2), PMP41130_CTRL (11 pins), PMP41130_AUX (C127.1 R128.1 U12.2 U12.4)
5V0_PRI: PMP41130_PWR (6 pins), PMP41130_AUX (C131.2 U14.2 U14.4)
5V0_SEC: PMP41130_PWR (10 pins), PMP41130_AUX (6 pins)
15V0_ACL: PMP41130_PWR (C146.2 U15.5), PMP41130_AUX (C150.1 C151.1 C152.1 L4.2)
GND: PMP41130_PWR (21 pins), PMP41130_CTRL (50 pins), PMP41130_AUX (20 pins)
VOUT: PMP41130_PWR (20 pins), PMP41130_CTRL (R71.2 R74.2)
DPWM0A: PMP41130_PWR (R44.2 R110.2), PMP41130_CTRL (U10.11)
DPWM0B: PMP41130_PWR (R65.2 R109.2), PMP41130_CTRL (U10.12)
DPWM1A: PMP41130_PWR (R66.2), PMP41130_CTRL (U10.13)
DPWM1B: PMP41130_PWR (R45.2), PMP41130_CTRL (U10.14)
DPWM2A: PMP41130_PWR (D4.1 D5.1 R43.1 R61.1), PMP41130_CTRL (U10.15)
DPWM2B: PMP41130_PWR (D3.1 D6.1 R42.1 R64.1), PMP41130_CTRL (U10.16)
DPWM3B: PMP41130_PWR (R132.1), PMP41130_CTRL (U10.18)
EAP2: PMP41130_PWR (R55.1), PMP41130_CTRL (C113.1 R100.1 U10.35)
OCP_Signal: PMP41130_PWR (C90.1 R52.1 R58.2), PMP41130_CTRL (U10.40)
PRI_AGND: PMP41130_PWR (12 pins), PMP41130_AUX (C131.1 U14.1)
SCP_Signal: PMP41130_PWR (C92.1 R55.2 R56.1 R60.2), PMP41130_CTRL (U10.2)
SR_Drain: PMP41130_PWR (10 pins), PMP41130_CTRL (R85.1), PMP41130_AUX (C150.2 C151.2 C152.2 T2.5)
VIN_NEG: PMP41130_PWR (39 pins), PMP41130_AUX (19 pins)
VIN_POS: PMP41130_PWR (9 pins), PMP41130_AUX (11 pins)
VIN_Scale: PMP41130_CTRL (U10.4), PMP41130_AUX (C140.1 R126.2)

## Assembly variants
001: not fitted FID1 FID2 FID3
